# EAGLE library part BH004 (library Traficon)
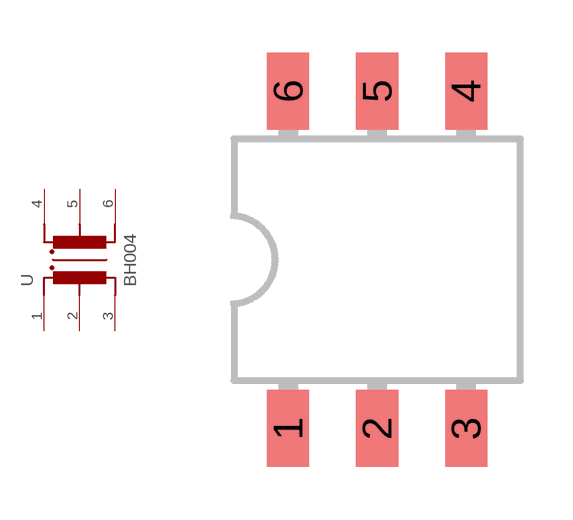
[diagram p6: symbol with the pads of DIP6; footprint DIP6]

Designator prefix -

## BH004  [DIP6]
1  1  pas
2  2  pas
3  3  pas
4  4  pas
5  5  pas
6  6  pas

## Footprint DIP6 (pad centres in mm)
SMD DIL08 dual in line package'
smd 1.2 x 2.2: 1 -2.54,-4.816; 2 0,-4.816; 3 2.54,-4.816; 4 2.54,4.816; 5 0,4.816; 6 -2.54,4.816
